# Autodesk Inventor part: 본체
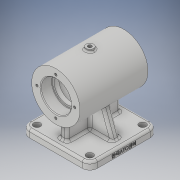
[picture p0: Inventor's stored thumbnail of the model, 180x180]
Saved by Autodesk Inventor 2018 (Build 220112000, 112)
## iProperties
Created: 2019-06
Part Number: 본체
Material: Generic
Document SubType Name: Modeling
Designer: Administrator
Density: 1 g/cm^3
Appearance: Default
Author: Administrator
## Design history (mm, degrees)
sketch "스케치1"
  geometry: C1 r 32 at (0, 0); 1 further point
  constraints: 1 centre point, 1 coincident
  dimensions: "d0" = 64 diameter of C1
extrude "돌출1" new body sketch "스케치1" stored distance "d1" = 90; taper "d2" = 0 deg
node "작업 평면1"
sketch "스케치2"
  geometry: L1 (45, 45)-(-45, 45); L2 (-45, 45)-(-45, -45); L3 (-45, -45)-(45, -45); L4 (45, -45)-(45, 45); L5 (45, 45)-(-45, -45); L6 (-45, 45)-(45, -45); 1 further point
  constraints: 12 end point, 2 midpoint, 2 parallel, 1 horizontal, 1 perpendicular
  dimensions: "d4" = 90 distance of L2.end L3.end; "d5" = 90 distance of L1.end L2.end
extrude "돌출2" join sketch "스케치2" distance "d6" = 10; taper "d7" = 0 deg
sketch "스케치3"
  geometry: L1 (45, -55)-(-45, -55) reference; L2 (-35, -55)-(-23.058, -22.189); L3 (-45, -65)-(-45, -55) reference; L4 (35, -55)-(23.058, -22.189); L5 (45, -65)-(45, -55) reference; L6 (-35, -55)-(35, -55); A1 r 32 centre (0, 0) between (-23.058, -22.189) and (23.058, -22.189); 1 further point
  constraints: 6 end point, 2 point on circle, 2 point on line, 1 centre point, 1 coincident, 1 collinear
  dimensions: "d8" = 110 deg angle of L2 L1; "d9" = 10 distance from line of L2.start L3; "d10" = 10 distance from line of L4.start L5; "d11" = 110 deg angle of L1 L4; "d12" = 64 diameter of A1
extrude "돌출3" join sketch "스케치3" stored distance "d13" = 10; taper "d14" = 0 deg
sketch "스케치4"
  geometry: L1 (-5, -35)-(5, -35); L2 (5, -35)-(5, 35); L3 (5, 35)-(-5, 35); L4 (-5, 35)-(-5, -35); L5 (-5, -35)-(5, 35); L6 (5, -35)-(-5, 35); 1 further point
  constraints: 12 end point, 2 midpoint, 2 parallel, 1 horizontal, 1 perpendicular
  dimensions: "d15" = 10 distance of L2.end L3.end; "d16" = 70 distance of L1.end L2.end
extrude "돌출4" join sketch "스케치4" stored distance "d17" = 10; taper "d18" = 0 deg
sketch "스케치5"
  geometry: L1 (0, 73.372)-(0, -73.372); L2 (20, 45)-(20, 30.6); L3 (19.4, 30)-(17, 30); L4 (17, 30)-(17, 24); L5 (17, 24)-(22, 24); L6 (25, 21)-(25, -21); L7 (22, -24)-(17, -24); L8 (17, -24)-(17, -30); L9 (17, -30)-(19.4, -30); L10 (20, -30.6)-(20, -45); L11 (-32, -45)-(32, -45) reference; L12 (20, -45)-(0, -45); L13 (32, 45)-(-32, 45) reference; L14 (0, 45)-(0, -45); L15 (0, 45)-(20, 45); A1 r 3 centre (22, -21) between (22, -24) and (25, -21); A2 r 3 centre (22, 21) between (25, 21) and (22, 24); A3 r 0.6 centre (19.4, -30.6) between (20, -30.6) and (19.4, -30); A4 r 0.6 centre (19.4, 30.6) between (19.4, 30) and (20, 30.6); 8 further points
  constraints: 26 end point, 12 point on line, 8 point on circle, 8 tangent, 7 perpendicular, 5 midpoint, 4 centre point, 3 vertical, 2 equal radius, 1 coincident, 1 collinear, 1 horizontal alignment
  dimensions: "d19" = 15 distance of L2.start point (20, 30); "d20" = 15 distance of point (20, -30) L10.end; "d21" = 48 distance of point (25, 24) point (25, -24); "d22" = 40 diameter of L2 L1; "d23" = 34 diameter of L4 L1; "d24" = 50 diameter of L6 L1; "d25" = 3 radius of A1 (derived); "d26" = 0.6 radius of A3
revolve "회전1" sketch "스케치5" stored, may be unused: angle "d27" = 90 deg
chamfer "모따기1" distance "d28" = 1; stored, may be unused: second distance "d29" = 2, angle "d30" = 45 deg
node "작업 평면2"
sketch "스케치6"
  geometry: C1 r 5 at (0, 0); 1 further point
  constraints: 1 centre point, 1 coincident
  dimensions: "d32" = 10 diameter of C1
extrude "돌출5" join sketch "스케치6" stored distance "d33" = 10; taper "d34" = 0 deg
sketch "스케치7"
  geometry: C1 r 5 at (0, 0) reference; 2 further points
  constraints: 1 coincident
hole "구멍1" sketch "스케치7" at (0, 0) diameter "d35" = 4.917; stored, may be unused: countersink angle "d39" = 90 deg, drill point angle "d41" = 118 deg; dims "d36" = 12, "d37" = 4, "d38" = 2, "d40" = 17.1
sketch "스케치8"
  geometry: C1 r 25 at (0, 0); 3 further points
  constraints: 2 vertical alignment, 1 centre point, 1 coincident, 1 other
  dimensions: "d42" = 50 diameter of C1
hole "구멍2" sketch "스케치8" at (0, 25) diameter "d43" = 3.242; stored, may be unused: countersink angle "d47" = 90 deg, drill point angle "d49" = 118 deg; dims "d44" = 7, "d45" = 4, "d46" = 2, "d48" = 9
fillet "모깎기1" dims "d53" = 10
sketch "스케치9"
  geometry: C1 r 4.5 at (-35, 35); C2 r 4.5 at (35, 35); C3 r 4.5 at (-35, -35); C4 r 4.5 at (35, -35); A1 r 10 centre (-35, 35) between (-35, 45) and (-45, 35) reference; A2 r 10 centre (35, 35) between (45, 35) and (35, 45) reference; A3 r 10 centre (-35, -35) between (-45, -35) and (-35, -45) reference; A4 r 10 centre (35, -35) between (35, -45) and (45, -35) reference; 1 further point
  constraints: 4 centre point, 4 coincident
  dimensions: "d54" = 9 diameter of C1; "d55" = 9 diameter of C2; "d56" = 9 diameter of C4; "d57" = 9 diameter of C3
extrude "돌출6" cut sketch "스케치9" distance "d58" = 10; taper "d59" = 0 deg
fillet "모깎기2" dims "d60" = 3
fillet "모깎기3" dims "d61" = 3
fillet "모깎기4" dims "d62" = 3
fillet "모깎기5" dims "d63" = 3
fillet "모깎기6" dims "d64" = 3
fillet "모깎기7" dims "d65" = 3
fillet "모깎기8" dims "d66" = 3
fillet "모깎기9" dims "d67" = 2
sketch "스케치10"
  geometry: L1 (0, 0)-(70, 0) reference; 2 further points
  constraints: 1 vertical alignment, 1 other
  dimensions: "d68" = 4 distance from line of point (35, 4) L1
feature "엠보싱1" sketch "스케치10" dims "d2" = 0, "d69" = 0.5, "d70" = 0
sketch "스케치11"
  geometry: L1 (22.155, 40)-(-22.155, 40); L2 (-40, 22.155)-(-40, -22.155); L3 (-22.155, -40)-(22.155, -40); L4 (40, -22.155)-(40, 22.155); L5 (40, 40)-(-40, -40); L6 (-40, 40)-(40, -40); C1 r 4.5 at (35, -35) reference; C2 r 4.5 at (35, 35) reference; C3 r 4.5 at (-35, 35) reference; A1 r 10 centre (35, -35) between (36.538, -25.119) and (25.119, -36.538); A2 r 10 centre (35, 35) between (25.119, 36.538) and (36.538, 25.119); A3 r 10 centre (-35, 35) between (-36.538, 25.119) and (-25.119, 36.538); A4 r 10 centre (-35, -35) between (-45, -35) and (-35, -45) reference; A5 r 10 centre (-35, -35) between (-25.119, -36.538) and (-36.538, -25.119); A6 r 3 centre (37, -22.155) between (36.538, -25.119) and (40, -22.155); A7 r 3 centre (22.155, -37) between (22.155, -40) and (25.119, -36.538); A8 r 3 centre (-22.155, -37) between (-25.119, -36.538) and (-22.155, -40); A9 r 3 centre (-37, -22.155) between (-40, -22.155) and (-36.538, -25.119); A10 r 3 centre (-22.155, 37) between (-22.155, 40) and (-25.119, 36.538); A11 r 3 centre (-37, 22.155) between (-36.538, 25.119) and (-40, 22.155); A12 r 3 centre (22.155, 37) between (25.119, 36.538) and (22.155, 40); A13 r 3 centre (37, 22.155) between (40, 22.155) and (36.538, 25.119); 10 further points
  constraints: 32 point on circle, 16 tangent, 12 centre point, 12 end point, 8 point on line, 7 equal radius, 4 coincident, 2 midpoint, 2 parallel, 1 horizontal, 1 perpendicular
  dimensions: "d71" = 80 distance of L5.end L6.end; "d72" = 80 distance of L6.start L5.end; "d73" = 20 diameter of A1; "d74" = 10 radius of A2; "d75" = 10 radius of A3; "d76" = 10 radius of A5; "d77" = 3 radius of A6; "d78" = 44.30953 distance of L3.start L3.end; "d79" = 44.30953 distance of L4.start L4.end; "d80" = 44.30953 distance of L2.start L2.end; "d81" = 44.30953 distance of L1.start L1.end
extrude "돌출7" cut sketch "스케치11" distance "d82" = 5; taper "d83" = 0 deg
node "솔리드1"
pattern_circular "원형 패턴1" dims angle "d51" = 360 deg
mirror "미러1"
other parameters: "d3" = -65, "d31" = 35
